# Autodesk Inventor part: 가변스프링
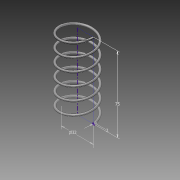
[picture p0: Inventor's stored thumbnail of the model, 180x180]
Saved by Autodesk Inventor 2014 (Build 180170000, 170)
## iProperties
Created: 2016-11
Part Number: 가변스프링
Material: 강철, 탄소
Document SubType Name: Modeling
Designer: NET
Density: 7.87 g/cm^3
Appearance: 반연마
Mass: 14.8293 g
Surface Area: 38.0156 cm^2
Volume: 1.88428 cm^3
Author: NET
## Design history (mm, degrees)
sketch "스케치1"
  geometry: L1 (0, 0)-(16, 0); L2 (16, 0)-(16, 75); L3 (16, 75)-(0, 75); L4 (0, 75)-(0, 0); C1 r 1 at (16, 0)
  constraints: 8 end point, 2 parallel, 1 centre point, 1 coincident, 1 horizontal, 1 perpendicular
  dimensions: "d0" = 32 diameter of L2 L4; "d1" = 2 diameter of C1; "d2" = 75 distance between parallel lines of L1 L3
feature "코일1" sketch "스케치1" pitch "d3" = 10; turns "d5" = 6; dims "d4" = 75 (= d2), "d6" = 0, angle "d7" = 90 deg, angle "d8" = 90 deg, "d9" = 0, "d10" = 0
sketch "스케치2"
  geometry: L1 (-17, 0)-(-15, 0) reference; 1 further point
  constraints: 1 horizontal alignment
extrude "돌출1" cut sketch "스케치2" distance "d11" = 10; taper "d12" = 0 deg
node "작업 평면1"
sketch "스케치3"
  geometry: L1 (-15, 0)-(-17, 0) reference; 1 further point
  constraints: 1 horizontal alignment
extrude "돌출2" cut sketch "스케치3" distance "d13" = 10; taper "d14" = 0 deg
node "솔리드1"
node "절단 모서리 투영1"
node "절단 모서리 투영2"
